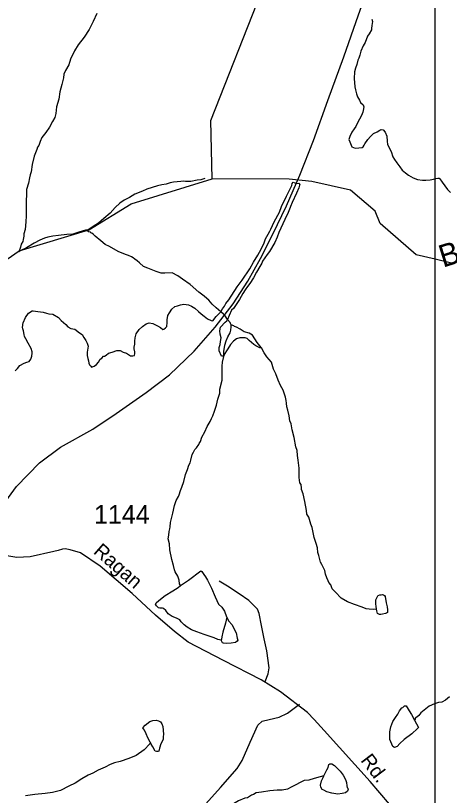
# Model space of a CAD drawing. Extents: x 2001466 to 2224147, y 644118 to 847247.
# Drawn here: x 2017667 to 2020568, y 713970 to 719190 of the extents above; entities that cross this region are included whole.
import ezdxf

# ---------------------------------------------------------------- set-up
doc = ezdxf.new("R2010")
doc.units = 0
for name, color, linetype in [('Exist Hydrographic Creek Single Shore', 7, 'Continuous'), ('Exist Hydrographic Creek Single Shore Label', 7, 'Continuous'), ('Exist Hydrographic Misc Water Feature', 7, 'Continuous'), ('Exist Railroad Mainline', 7, 'Continuous'), ('Exist Road Non-System Type 51', 7, 'Continuous'), ('Exist Road Secondary Type 51 Attributed', 7, 'Continuous'), ('Exist Road Secondary Type 51 Label', 7, 'Continuous'), ('Exist Road Secondary Type 51 Number Label', 7, 'Continuous'), ('Map Preparation Inset Cut Line', 7, 'Continuous')]:
    doc.layers.add(name, color=color, linetype=linetype)

msp = doc.modelspace()

# ---------------------------------------------------------------- linework, layer by layer
at = {"layer": 'Exist Hydrographic Creek Single Shore'}
for p, q in [((2019497.1, 718095.8), (2018981.2, 718096.5)), ((2019647.2, 718079.6), (2019497.1, 718095.8))]:
    msp.add_line(p, q, dxfattribs=at)
for points in [[(2018981.2, 718096.5), (2018972.1, 718487.2), (2019313.1, 719356.2), (2019338.2, 719470.5)], [(2016457.2, 716996.2), (2016673.1, 717044.4), (2016973.1, 717212.1), (2017265.1, 717321), (2017690.1, 717614.3), (2018156, 717755.6), (2018439.2, 717930.3), (2018981.2, 718096.5)], [(2020472.9, 717558.8), (2020347, 717589.6), (2020106.1, 717798), (2020072, 717880.7), (2019906.1, 718021.9), (2019647.2, 718079.6)], [(2021689.1, 717457.2), (2021364.1, 717723), (2021081.1, 717699.3), (2020581.2, 717532.3), (2020472.9, 717558.8)]]:
    msp.add_lwpolyline(points, dxfattribs=at)
at = {"layer": 'Exist Hydrographic Misc Water Feature'}
for points in [[(2018210.4, 719203), (2018186.4, 719151), (2018158.5, 719097), (2018126.5, 719045), (2018086.5, 718995), (2018060.5, 718954.9), (2018034.4, 718899), (2018022.5, 718860.9), (2018000.6, 718822.9), (2017990.6, 718797), (2017986.7, 718773), (2017976.6, 718728.9), (2017962.7, 718678.9), (2017956.7, 718631), (2017940.7, 718578.9), (2017936.8, 718534.9), (2017928.8, 718507), (2017914.7, 718481), (2017894.8, 718442.9), (2017869, 718406.9), (2017842.9, 718373), (2017830.8, 718346.9), (2017822.8, 718320.9), (2017812.8, 718308.9), (2017808.9, 718292.9), (2017791, 718248.9), (2017778.9, 718192.9), (2017770.9, 718144.9), (2017765, 718124.9), (2017760.9, 718102.9), (2017753.1, 718068.9), (2017739.2, 718024.9), (2017739.2, 717990.9), (2017737.1, 717953), (2017737.1, 717898.9), (2017737.3, 717848.9), (2017735.3, 717809), (2017731.2, 717758.9), (2017723.2, 717728.9), (2017721.3, 717712.9), (2017717.2, 717691), (2017715.2, 717677), (2017705.3, 717658.9), (2017699.4, 717640.9), (2017689.3, 717608.9)], [(2020050.1, 719166.1), (2020054.2, 719150.1), (2020050.1, 719124.2), (2020046.2, 719104.2), (2020046.2, 719094.2), (2020032.3, 719068.2), (2020020.2, 719052.1), (2020004.2, 719010.1), (2019992.3, 718988.1), (2019976.3, 718952.1), (2019970.3, 718924.1), (2019962.3, 718904.1), (2019956.2, 718892.1), (2019948.4, 718862.1), (2019940.4, 718838.1), (2019934.4, 718814.1), (2019930.3, 718768.1), (2019936.3, 718712.1), (2019940.4, 718692.1), (2019946.5, 718666.1), (2019954.5, 718646.2), (2019966.4, 718624.1), (2019974.4, 718608.2), (2019992.5, 718592.2), (2019996.6, 718580.2), (2019992.5, 718554.2), (2019988.6, 718544.2), (2019984.5, 718532.2), (2019980.6, 718522.2), (2019954.5, 718472.2), (2019942.6, 718448.2), (2019930.5, 718432.2), (2019916.6, 718410.2), (2019902.7, 718380.2), (2019896.5, 718360.1), (2019902.7, 718344.1), (2019916.6, 718312.2), (2019938.5, 718302.2), (2019962.5, 718304.2), (2019984.7, 718306.2), (2019990.6, 718312.2), (2019998.6, 718322.2), (2020002.5, 718332.2), (2020022.6, 718360.2), (2020040.7, 718380.2), (2020060.6, 718400.2), (2020084.5, 718412.2), (2020102.6, 718422.3), (2020112.6, 718428.3), (2020124.5, 718424.3), (2020138.7, 718410.3), (2020150.6, 718382.3), (2020152.6, 718350.3), (2020154.7, 718326.3), (2020162.7, 718312.3), (2020170.7, 718296.3), (2020178.7, 718280.3), (2020190.6, 718244.3), (2020200.6, 718226.3), (2020216.6, 718204.4), (2020236.7, 718178.4), (2020252.7, 718154.4), (2020274.6, 718138.4), (2020294.7, 718122.4), (2020326.7, 718104.4), (2020354.8, 718092.4), (2020388.6, 718088.5), (2020410.8, 718088.5), (2020438.7, 718090.5), (2020460.8, 718094.5), (2020476.8, 718098.5), (2020490.8, 718102.5), (2020498.7, 718102.5), (2020504.7, 718096.5), (2020520.7, 718074.6), (2020536.7, 718050.6), (2020554.7, 718026.6), (2020574.6, 718006.5)], [(2018932.8, 718099.6), (2018904.9, 718091.6), (2018880.9, 718087.6), (2018838.9, 718079.6), (2018802.8, 718079.5), (2018790.9, 718081.5), (2018772.8, 718079.5), (2018723, 718075.5), (2018701.1, 718071.5), (2018675, 718061.4), (2018645.1, 718057.4), (2018617, 718051.4), (2018580.9, 718039.4), (2018545, 718027.4), (2018515.1, 718015.3), (2018465, 717995.3), (2018429, 717973.3), (2018393.1, 717955.3), (2018365.2, 717935.3), (2018333.2, 717905.3), (2018299.2, 717867.2), (2018257.1, 717831.2), (2018221, 717801.2), (2018193.1, 717783.2), (2018151.3, 717753.2), (2018141.3, 717753.1)], [(2019039.4, 717207.8), (2019051.3, 717227.8), (2019063.4, 717245.8), (2019073.4, 717261.8), (2019093.3, 717287.8), (2019149.3, 717373.8), (2019183.1, 717417.8), (2019233.2, 717495.8), (2019257.2, 717539.8), (2019287.1, 717585.8), (2019309, 717625.9), (2019329.1, 717667.9), (2019339.2, 717695.9), (2019355.2, 717725.9), (2019367.1, 717747.9), (2019373, 717759.9), (2019397, 717809.9), (2019431, 717874), (2019444.8, 717911.9), (2019478.8, 717981.9), (2019514.9, 718051.9), (2019516.8, 718065.9), (2019522.9, 718074), (2019544.8, 718066), (2019560.8, 718068), (2019568.8, 718061.9), (2019566.8, 718055.9), (2019560.8, 718038), (2019544.8, 718002), (2019516.8, 717938), (2019505.1, 717912), (2019503, 717906), (2019489.1, 717872), (2019466.9, 717824), (2019440.9, 717768), (2019426.9, 717738), (2019417.1, 717705.9), (2019401.1, 717672), (2019365, 717611.9), (2019349, 717589.9), (2019319.1, 717545.9), (2019313.1, 717531.9), (2019301.2, 717509.9), (2019279.3, 717471.9), (2019257.2, 717433.9), (2019233.2, 717395.9), (2019217.2, 717375.8), (2019203.4, 717353.8), (2019187.2, 717329.9), (2019165.3, 717289.8), (2019123.3, 717229.8), (2019111.4, 717217.8), (2019095.4, 717181.8), (2019083.3, 717155.8)], [(2018141.3, 717753.1), (2018135.3, 717753.1), (2018091.2, 717741.1), (2018049.2, 717727.1), (2018009.2, 717725.1), (2017953.2, 717717), (2017917.1, 717713), (2017883.3, 717707), (2017861.2, 717699), (2017829.2, 717687), (2017791.2, 717667), (2017739.2, 717634.9), (2017697.3, 717614.9), (2017689.3, 717608.9)], [(2019039.4, 717207.8), (2019007.4, 717233.8), (2018981.4, 717257.7), (2018959.4, 717285.7), (2018945.3, 717295.7), (2018927.4, 717311.7), (2018893.4, 717339.6), (2018835.2, 717389.6), (2018783.3, 717425.6), (2018751.3, 717447.6), (2018715.2, 717467.6), (2018665.2, 717465.5), (2018641.2, 717465.5), (2018607.1, 717477.4), (2018551.2, 717499.4), (2018523.3, 717511.4), (2018495.2, 717535.4), (2018479.2, 717547.4), (2018465.2, 717559.4), (2018453.1, 717567.4), (2018441.3, 717575.4), (2018421.2, 717583.4), (2018403.3, 717591.4), (2018353.3, 717611.3), (2018295.3, 717645.3), (2018265.3, 717657.3), (2018237.2, 717681.2), (2018199.3, 717713.2), (2018187.2, 717725.2), (2018177.1, 717733.2), (2018171.2, 717735.2), (2018167.3, 717739.2), (2018155.2, 717743.2), (2018141.3, 717753.1)], [(2017715.6, 717115), (2017715.6, 717121), (2017717.6, 717133), (2017733.6, 717169), (2017753.5, 717197), (2017777.5, 717213), (2017785.5, 717213), (2017815.6, 717209), (2017851.5, 717205.1), (2017873.5, 717199.1), (2017889.5, 717193.1), (2017915.5, 717191.1), (2017953.6, 717169.1), (2017971.7, 717149.1), (2018003.7, 717121.2), (2018015.6, 717107.2), (2018037.5, 717095.2), (2018063.5, 717091.2), (2018093.5, 717067.2), (2018111.5, 717055.2), (2018123.6, 717035.2), (2018137.6, 717015.3), (2018145.6, 716997.3), (2018151.5, 716977.3), (2018147.6, 716949.3), (2018145.6, 716937.2), (2018145.8, 716915.2), (2018149.7, 716895.3), (2018155.6, 716879.3), (2018157.7, 716863.3), (2018161.8, 716851.3), (2018169.8, 716843.3), (2018175.7, 716837.3), (2018191.7, 716843.3), (2018207.7, 716855.3), (2018221.6, 716869.3), (2018233.7, 716889.3), (2018243.8, 716897.3), (2018255.5, 716909.4), (2018261.6, 716909.3), (2018273.5, 716917.4), (2018287.7, 716929.3), (2018313.5, 716937.4), (2018343.7, 716947.4), (2018367.6, 716947.4), (2018387.5, 716937.4), (2018409.7, 716929.4), (2018435.5, 716913.4), (2018451.5, 716911.5), (2018461.6, 716915.4), (2018465.7, 716927.4), (2018465.7, 716939.4), (2018459.5, 716959.4), (2018459.5, 716971.4), (2018463.6, 716991.5), (2018463.6, 717011.5), (2018467.5, 717033.5), (2018473.4, 717059.4), (2018493.5, 717089.4), (2018515.5, 717109.4), (2018539.5, 717125.5), (2018559.4, 717133.5), (2018585.4, 717129.5), (2018615.5, 717113.5), (2018635.4, 717101.5), (2018651.4, 717089.6), (2018659.4, 717091.6), (2018669.5, 717099.6), (2018679.5, 717109.6), (2018681.4, 717135.6), (2018681.4, 717153.6), (2018685.5, 717181.6), (2018695.5, 717199.6), (2018711.5, 717225.6), (2018731.4, 717241.6), (2018749.2, 717247.6), (2018769.3, 717253.6), (2018793.3, 717257.6), (2018823.3, 717253.6), (2018843.4, 717245.6), (2018865.3, 717231.6), (2018891.3, 717209.7), (2018907.5, 717193.7), (2018929.3, 717177.7), (2018951.4, 717159.7), (2018975.4, 717149.7), (2018985.3, 717145.8), (2019009.5, 717175.8), (2019039.4, 717207.8)], [(2019083.3, 717155.8), (2019069.3, 717179.8), (2019057.2, 717191.8), (2019039.4, 717207.8)], [(2019059.5, 716911.9), (2019055.6, 716909.8), (2019043.5, 716909.8), (2019029.3, 716945.8), (2019029.5, 716967.8), (2019035.5, 716987.8), (2019037.5, 717007.8), (2019041.4, 717031.8), (2019035.5, 717057.8), (2019033.4, 717079.8), (2019037.5, 717103.8), (2019069.3, 717137.8), (2019079.4, 717145.8), (2019083.3, 717155.8)], [(2019059.5, 716911.9), (2019059.5, 716941.8), (2019067.5, 716983.8), (2019075.5, 717011.8), (2019087.4, 717039.8), (2019101.5, 717065.9), (2019107.5, 717083.8), (2019109.5, 717105.8), (2019108.5, 717118.9), (2019105.4, 717127.8)], [(2019105.4, 717127.8), (2019101.5, 717135.8), (2019083.3, 717155.8)], [(2019311.5, 716965.9), (2019299.4, 716980), (2019283.4, 717002), (2019267.4, 717025.9), (2019251.4, 717049.9), (2019229.5, 717063.9), (2019195.4, 717073.9), (2019181.5, 717081.9), (2019169.4, 717091.8), (2019145.4, 717103.8), (2019131.5, 717109.8), (2019127.4, 717113.8), (2019108.5, 717118.9), (2019105.4, 717127.8)], [(2017663.7, 716811), (2017679.7, 716827), (2017695.7, 716847), (2017723.8, 716863.1), (2017741.6, 716869.1), (2017757.6, 716875.1), (2017769.7, 716889), (2017775.7, 716911), (2017777.7, 716931.1), (2017777.7, 716939.1), (2017771.8, 716961.1), (2017751.7, 716997), (2017735.7, 717027), (2017727.7, 717041), (2017725.6, 717055), (2017719.7, 717079), (2017715.6, 717093), (2017713.5, 717105), (2017715.6, 717115)], [(2019311.5, 716965.9), (2019301.4, 716965.9), (2019273.4, 716979.9), (2019259.4, 716987.9), (2019229.5, 717013.9), (2019215.5, 717027.9), (2019203.4, 717031.9), (2019187.4, 717033.9), (2019167.5, 717031.8), (2019143.4, 717025.8), (2019123.5, 717009.8), (2019103.4, 716987.8), (2019087.4, 716959.8), (2019077.5, 716945.8), (2019065.6, 716927.9), (2019059.5, 716911.9)], [(2020080.2, 715216.6), (2020060.3, 715214.6), (2020032.3, 715216.6), (2020012.4, 715218.6), (2019984.5, 715230.6), (2019934.2, 715248.5), (2019886.3, 715264.5), (2019844.2, 715290.5), (2019806.3, 715330.4), (2019784.3, 715352.5), (2019774.3, 715378.5), (2019762.2, 715394.5), (2019758.3, 715406.4), (2019748.3, 715426.4), (2019740.3, 715450.4), (2019734.3, 715474.4), (2019714.2, 715516.4), (2019706.2, 715530.3), (2019694.1, 715576.4), (2019688.2, 715596.3), (2019686.1, 715626.3), (2019676.1, 715656.3), (2019664.2, 715696.4), (2019656.2, 715730.4), (2019650, 715762.3), (2019642, 715786.3), (2019628.1, 715832.3), (2019613.9, 715852.3), (2019612.1, 715876.3), (2019602.1, 715938.3), (2019590, 715988.3), (2019579.9, 716018.3), (2019579.9, 716026.2), (2019577.9, 716050.2), (2019568, 716062.2), (2019563.9, 716098.2), (2019563.9, 716160.2), (2019557.8, 716214.2), (2019551.8, 716246.2), (2019549.8, 716278.2), (2019541.8, 716304.2), (2019529.9, 716366.2), (2019517.8, 716416.1), (2019509.6, 716458.1), (2019501.6, 716478.1), (2019495.6, 716510.2), (2019487.6, 716548.1), (2019481.7, 716570.1), (2019479.6, 716596.1), (2019475.5, 716614.1), (2019473.7, 716624.1), (2019471.6, 716636.1), (2019455.6, 716682.1), (2019439.7, 716714.1), (2019423.7, 716750), (2019407.7, 716792), (2019391.5, 716824), (2019377.5, 716870), (2019347.4, 716906), (2019329.5, 716932), (2019311.5, 716965.9)], [(2018770.4, 715373.8), (2018764.4, 715385.8), (2018760.3, 715409.8), (2018752.3, 715437.8), (2018734.5, 715465.8), (2018730.4, 715479.8), (2018722.4, 715509.8), (2018712.3, 715549.8), (2018698.2, 715613.8), (2018696.3, 715653.8), (2018688.3, 715687.8), (2018692.2, 715711.7), (2018694.1, 715735.8), (2018698.2, 715753.8), (2018700.2, 715767.8), (2018702.1, 715795.7), (2018718.1, 715859.8), (2018730.2, 715909.8), (2018742.1, 715943.8), (2018756, 715969.7), (2018760.1, 715981.7), (2018770, 716009.8), (2018778, 716033.8), (2018792.1, 716071.8), (2018804, 716117.7), (2018817.9, 716151.8), (2018825.9, 716179.8), (2018833.9, 716195.8), (2018839.9, 716213.8), (2018847.9, 716251.7), (2018857.9, 716267.8), (2018865.9, 716285.8), (2018878, 716295.8), (2018892, 716319.8), (2018895.9, 716325.8), (2018903.9, 716339.8), (2018911.8, 716367.8), (2018931.7, 716403.8), (2018947.7, 716439.8), (2018967.8, 716471.8), (2018977.9, 716491.8), (2018985.9, 716509.9), (2018997.8, 716541.8), (2019009.7, 716581.8), (2019019.7, 716621.8), (2019033.7, 716661.8), (2019033.7, 716689.8), (2019049.6, 716749.8), (2019047.6, 716789.9), (2019049.6, 716815.8), (2019049.6, 716831.8), (2019049.6, 716843.8), (2019051.5, 716869.8), (2019059.5, 716907.8), (2019059.5, 716911.9)], [(2018770.4, 715373.8), (2018822.4, 715409.8), (2018906.3, 715473.9), (2018912.3, 715467.9), (2018926.2, 715447.9), (2018936.5, 715431.9), (2018950.4, 715410), (2018976.4, 715356), (2019002.5, 715297.9), (2019024.4, 715250), (2019046.6, 715230), (2019064.6, 715202), (2019078.6, 715166), (2019080.6, 715162.1)], [(2019042.7, 715008.1), (2019020.5, 715014), (2018994.7, 715024), (2018954.7, 715038), (2018928.5, 715047.9), (2018878.4, 715063.9), (2018844.6, 715077.9), (2018814.4, 715095.9), (2018794.6, 715111.9), (2018774.5, 715131.9), (2018764.6, 715145.8), (2018742.5, 715155.8), (2018714.6, 715167.8), (2018688.5, 715185.8), (2018672.6, 715207.8), (2018656.6, 715219.8), (2018650.6, 715223.8), (2018632.6, 715223.8), (2018622.5, 715225.8), (2018610.4, 715239.8), (2018602.4, 715249.8), (2018606.5, 715257.8), (2018624.6, 715273.7), (2018666.6, 715307.7), (2018718.5, 715339.8), (2018754.4, 715361.8), (2018770.4, 715373.8)], [(2020080.2, 715216.6), (2020078.2, 715236.6), (2020076.3, 715250.6), (2020076.3, 715278.6), (2020084.3, 715296.6), (2020090.3, 715304.7), (2020092.3, 715308.7), (2020102.2, 715312.7), (2020112.2, 715312.6), (2020120.2, 715314.7), (2020128.2, 715312.7), (2020134.2, 715308.7), (2020138.3, 715300.7), (2020146.3, 715258.7), (2020152.2, 715232.6), (2020154.5, 715212.6), (2020154.3, 715202.6), (2020154.3, 715194.7), (2020148.3, 715190.7), (2020140.3, 715186.7), (2020120.4, 715182.7), (2020110.4, 715180.7), (2020100.3, 715180.7), (2020088.4, 715186.7), (2020082.3, 715204.6), (2020080.2, 715216.6)], [(2019080.6, 715162.1), (2019070.6, 715122), (2019052.5, 715062.1), (2019046.6, 715030.1), (2019044.5, 715016.1), (2019042.7, 715008.1)], [(2019080.6, 715162.1), (2019090.4, 715138.1), (2019114.4, 715112.1), (2019126.5, 715088.1), (2019142.5, 715058.1), (2019148.5, 715022.1), (2019152.6, 715008.1), (2019148.7, 715002.2), (2019138.4, 714994.1), (2019108.7, 714988.1), (2019074.7, 714986.1), (2019056.6, 714988), (2019050.7, 714992), (2019046.6, 715000), (2019042.7, 715008.1)], [(2020568.7, 714629), (2020542.6, 714607), (2020516.6, 714593), (2020494.6, 714591), (2020468.6, 714583), (2020432.5, 714566.9), (2020398.7, 714540.9), (2020376.7, 714522.9), (2020362.8, 714504.9), (2020350.7, 714492.9), (2020338.8, 714486.9), (2020338.8, 714478.9), (2020334.7, 714472.9)], [(2020334.7, 714472.9), (2020360.7, 714424.9), (2020354.8, 714416.9), (2020316.7, 714382.9), (2020264.8, 714342.9), (2020236.7, 714316.9), (2020218.9, 714296.8), (2020200.8, 714290.8), (2020188.9, 714296.8), (2020170.7, 714344.8), (2020170.7, 714368.8), (2020170.7, 714394.8), (2020176.8, 714428.8), (2020190.8, 714464.8), (2020208.8, 714490.8), (2020222.7, 714512.8), (2020234.6, 714534.8), (2020250.8, 714554.8), (2020256.6, 714558.8), (2020268.7, 714568.8), (2020278.5, 714568.8), (2020286.5, 714558.8), (2020298.6, 714536.8), (2020314.8, 714510.9), (2020334.7, 714472.9)], [(2018571.1, 714319.8), (2018567, 714325.9), (2018551, 714355.8), (2018540.9, 714381.8), (2018529, 714405.8), (2018523.1, 714415.8), (2018519, 714421.8), (2018532.9, 714439.8), (2018564.9, 714463.8), (2018584.8, 714471.8), (2018606.9, 714473.8), (2018622.9, 714469.8), (2018636.9, 714461.9), (2018644.9, 714447.9), (2018650.8, 714429.9), (2018657, 714379.9), (2018654.9, 714361.9), (2018653.1, 714343.9), (2018638.9, 714315.9), (2018629.1, 714285.9), (2018625, 714265.9), (2018619, 714263.9), (2018609, 714263.9), (2018601, 714265.9), (2018585, 714293.9), (2018574.9, 714311.8), (2018571.1, 714319.8)], [(2018571.1, 714319.8), (2018564.9, 714315.8), (2018527, 714275.8), (2018473, 714237.8), (2018425.1, 714217.7), (2018367, 714197.7), (2018329.1, 714187.7), (2018299.2, 714175.7), (2018267.2, 714157.7), (2018219.2, 714139.6), (2018183.1, 714117.6), (2018153.2, 714105.6), (2018111.3, 714081.6), (2018065.2, 714051.5), (2018023.2, 714031.5), (2017967.2, 714003.6), (2017913.2, 713989.5), (2017865.5, 713981.4), (2017795.3, 713975.4), (2017733.4, 713967.4)], [(2019729, 714100.5), (2019731, 714104.5), (2019737, 714118.6), (2019749.1, 714140.6), (2019757.1, 714156.6), (2019763, 714176.6), (2019769, 714180.6), (2019777, 714180.6), (2019781.1, 714180.6), (2019798.9, 714170.6), (2019822.9, 714148.6), (2019837, 714132.6), (2019856.9, 714104.6), (2019872.9, 714076.7), (2019879.1, 714056.7), (2019883, 714034.7), (2019885, 714022.7), (2019888.9, 714018.7), (2019891, 714010.7), (2019887.1, 713998.6), (2019873.1, 713986.6), (2019851.2, 713982.6), (2019821.1, 713978.6), (2019781.1, 713984.6), (2019749.1, 713994.6), (2019729, 714004.6), (2019717.1, 714008.6), (2019708.9, 714024.6), (2019707, 714038.6), (2019713, 714066.6), (2019723, 714088.6), (2019729, 714100.5)], [(2019729, 714100.5), (2019702.9, 714094.5), (2019663, 714082.6), (2019627.1, 714072.5), (2019596.9, 714070.5), (2019578.9, 714060.5), (2019533.2, 714036.5), (2019511, 714024.5), (2019485.2, 714012.5), (2019449.1, 714004.4), (2019417.1, 714004.4), (2019367.1, 714000.4), (2019311.1, 713992.3), (2019275.2, 713986.3), (2019257.2, 713976.3), (2019245.1, 713970.3), (2019217.2, 713954.3), (2019201.2, 713950.3), (2019157.1, 713934.2), (2019123.3, 713914.2), (2019095.2, 713886.2), (2019085.3, 713868.2), (2019071.2, 713858.2)]]:
    msp.add_lwpolyline(points, dxfattribs=at)
at = {"layer": 'Exist Railroad Mainline'}
msp.add_lwpolyline([(2017428.6, 715631.9), (2017473.9, 715736), (2017547.3, 715866.3), (2017672.8, 716036.8), (2017826.1, 716195.3), (2017967.9, 716301.8), (2018183.3, 716420.6), (2018338.8, 716525.2), (2018540.4, 716667.9), (2018696, 716784.4), (2018861.4, 716943), (2019000.9, 717103.6), (2019122.3, 717260), (2019219.8, 717412.4), (2019305.1, 717564.7), (2019386.6, 717727), (2019477.9, 717917.2), (2019567.3, 718121.6), (2019658.5, 718353.9), (2019755.5, 718622.2), (2019862.5, 718914.6), (2019959.4, 719194.9), (2020331.8, 720230.2), (2020333.6, 720235.3)], dxfattribs=at)
at = {"layer": 'Exist Road Non-System Type 51'}
for points in [[(2019337, 714731.9), (2019357, 714782.8), (2019362.4, 714822.9), (2019346.3, 714936.5), (2019330.3, 715018), (2019310.8, 715106.8), (2019295.9, 715188.2), (2019285.1, 715216.1), (2019227.3, 715273.9), (2019163.1, 715318.9), (2019083.9, 715370.3), (2019028.6, 715404.7)], [(2018918.5, 713891.9), (2019037.4, 714022.3), (2019149.5, 714150.6), (2019181.6, 714202.7), (2019235, 714325.6), (2019287.6, 714439.4), (2019317, 714466.2), (2019363.7, 714476.9), (2019429.1, 714492.9), (2019486.5, 714519.6), (2019565.1, 714580.3)]]:
    msp.add_lwpolyline(points, dxfattribs=at)
at = {"layer": 'Exist Road Secondary Type 51 Attributed'}
msp.add_lwpolyline([(2020361, 713683.2), (2020038.1, 714061.8), (2019730.4, 714405), (2019664.8, 714478.2), (2019619.4, 714523.6), (2019437.8, 714662.4), (2019309.1, 714743.2), (2019056.9, 714871.9), (2018822.3, 714995.6), (2018728.9, 715066.2), (2018602.8, 715177.3), (2018446.4, 715321.1), (2018233.2, 715504.7), (2018101.6, 715592.5), (2018032.6, 715613.2), (2017998.7, 715619.5), (2017980.5, 715619.2), (2017952.9, 715610.1), (2017922.7, 715602.4), (2017765.3, 715566.1), (2017675.8, 715563.2), (2017609.7, 715574.1)], dxfattribs=at)
at = {"layer": 'Map Preparation Inset Cut Line'}
for p, q in [((2020472.9, 717558.8), (2020472.9, 720186.2)), ((2020472.9, 713518.1), (2020472.9, 717558.8))]:
    msp.add_line(p, q, dxfattribs=at)

# ---------------------------------------------------------------- texts
at = {"layer": 'Exist Hydrographic Creek Single Shore Label'}
msp.add_text('Beaver', height=150, rotation=17.3667, dxfattribs=at).set_placement((2020525, 717502.1))
at = {"layer": 'Exist Road Secondary Type 51 Label'}
for s, rotation, p in [('Ragan', 318.8134, (2018181.6, 715594.1)), ('Rd.', 307.0555, (2019970.6, 714203.3))]:
    msp.add_text(s, height=95, rotation=rotation, dxfattribs=at).set_placement(p)
at = {"layer": 'Exist Road Secondary Type 51 Number Label'}
msp.add_text('1144', height=125, dxfattribs=at).set_placement((2018191.6, 715788.1))

doc.saveas('drawing.dxf')
